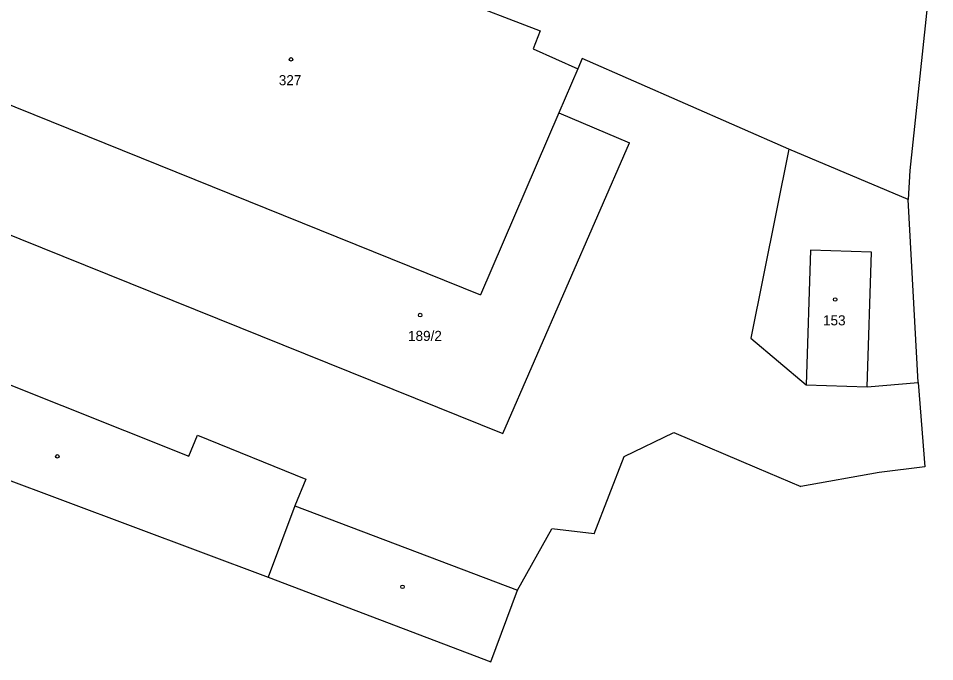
# Model space of a CAD drawing. Extents: x -643859 to -643594, y -1190913 to -1190609.
# Drawn here: x -643684.5 to -643593.8, y -1190869.1 to -1190805.4 of the extents above; entities that cross this region are included whole.
import ezdxf

# ---------------------------------------------------------------- set-up
doc = ezdxf.new("R2010")
doc.units = 0
for name, color, linetype in [('Hranice parcel', 7, 'Continuous'), ('Vrstva 1', 7, 'Continuous'), ('Vrstva 11', 7, 'Continuous'), ('Vrstva 38', 7, 'Continuous'), ('Vrstva 63', 7, 'Continuous')]:
    doc.layers.add(name, color=color, linetype=linetype)

msp = doc.modelspace()

# ---------------------------------------------------------------- linework, layer by layer
at = {"layer": 'Hranice parcel'}
for p, q in [((-643664.89, -1190794.26), (-643632.83, -1190806.65)), ((-643593.79, -1190797.13), (-643596.24, -1190820.47)), ((-643632.83, -1190806.65), (-643633.52, -1190808.42)), ((-643633.52, -1190808.42), (-643629.1, -1190810.39)), ((-643628.66, -1190809.36), (-643629.1, -1190810.39)), ((-643608.22, -1190818.34), (-643628.66, -1190809.36)), ((-643693.65, -1190810.62), (-643638.73, -1190832.74)), ((-643629.1, -1190810.39), (-643630.98, -1190814.74)), ((-643630.98, -1190814.74), (-643638.73, -1190832.74)), ((-643608.22, -1190818.34), (-643612, -1190837.06)), ((-643596.42, -1190823.34), (-643608.22, -1190818.34)), ((-643596.24, -1190820.47), (-643596.42, -1190823.34)), ((-643595.43, -1190841.42), (-643596.42, -1190823.34)), ((-643612, -1190837.06), (-643606.51, -1190841.66)), ((-643606.51, -1190841.66), (-643600.46, -1190841.86)), ((-643600.46, -1190841.86), (-643595.43, -1190841.42)), ((-643595.43, -1190841.42), (-643594.77, -1190849.78)), ((-643704.91, -1190843.78), (-643659.76, -1190860.7)), ((-643624.51, -1190848.74), (-643619.61, -1190846.37)), ((-643619.61, -1190846.37), (-643611.38, -1190849.87)), ((-643627.5, -1190856.39), (-643624.51, -1190848.74)), ((-643611.38, -1190849.87), (-643607.04, -1190851.72)), ((-643594.77, -1190849.78), (-643599.28, -1190850.33)), ((-643599.28, -1190850.33), (-643607.04, -1190851.72)), ((-643635.06, -1190861.98), (-643631.67, -1190855.91)), ((-643627.5, -1190856.39), (-643631.67, -1190855.91)), ((-643659.76, -1190860.7), (-643637.73, -1190869.05)), ((-643637.73, -1190869.05), (-643635.06, -1190861.98))]:
    msp.add_line(p, q, dxfattribs=at)
at = {"layer": 'Vrstva 1'}
for p, q in [((-643630.98, -1190814.74), (-643623.99, -1190817.73)), ((-643636.53, -1190846.47), (-643623.99, -1190817.73)), ((-643698.1, -1190821.69), (-643636.53, -1190846.47)), ((-643606.08, -1190828.34), (-643606.51, -1190841.66)), ((-643600.03, -1190828.54), (-643606.08, -1190828.34)), ((-643600.46, -1190841.86), (-643600.03, -1190828.54)), ((-643697.93, -1190836.66), (-643667.6, -1190848.71)), ((-643667.6, -1190848.71), (-643666.76, -1190846.65)), ((-643666.76, -1190846.65), (-643656.03, -1190851.01)), ((-643656.03, -1190851.01), (-643657.1, -1190853.64)), ((-643657.1, -1190853.64), (-643659.76, -1190860.7)), ((-643657.1, -1190853.64), (-643635.06, -1190861.98))]:
    msp.add_line(p, q, dxfattribs=at)
at = {"layer": 'Vrstva 11'}
for centre in [(-643657.5, -1190809.46), (-643603.64, -1190833.22), (-643644.71, -1190834.76)]:
    msp.add_circle(centre, 0.175, dxfattribs=at)
at = {"layer": 'Vrstva 38'}
for centre in [(-643680.62, -1190848.74), (-643646.46, -1190861.64)]:
    msp.add_circle(centre, 0.175, dxfattribs=at)

# ---------------------------------------------------------------- texts
at = {"layer": 'Vrstva 63'}
for s, p in [('327', (-643658.699, -1190812.019)), ('153', (-643604.839, -1190835.779)), ('189/2', (-643645.909, -1190837.319))]:
    msp.add_text(s, height=1, dxfattribs=at).set_placement(p)

doc.saveas('drawing.dxf')
